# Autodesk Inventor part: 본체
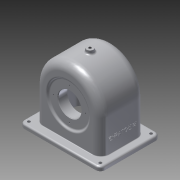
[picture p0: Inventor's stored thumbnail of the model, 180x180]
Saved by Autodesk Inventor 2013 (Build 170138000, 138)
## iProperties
Created: 2016-01
Part Number: 본체
Material: 알루미늄 6061
Document SubType Name: Modeling
Designer: cad10
Density: 2.40731 g/cm^3
Mass: 807.483 g
Surface Area: 1019.49 cm^2
Volume: 335.429 cm^3
Author: cad10
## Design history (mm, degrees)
sketch "스케치1"
  geometry: L1 (57, 0)-(57, -64); L2 (57, -64)-(-57, -64); L3 (-57, -64)-(-57, 0); L4 (0, 12.214)-(0, 34.551); A1 r 57 centre (0, 0) between (57, 0) and (-57, 0); 1 further point
  constraints: 8 end point, 2 parallel, 2 point on circle, 1 centre point, 1 coincident, 1 other
  dimensions: "d1" = 57 radius of A1; "d3" = 114 distance of L3.end L1.start; "d4" = 64 distance of L1.start L1.end
extrude "돌출1" new body sketch "스케치1" distance "d5" = 77; taper "d6" = 0 deg
node "작업 평면1"
sketch "스케치2"
  geometry: L1 (57, 0)-(-57, 0) reference; L2 (-57, 0)-(-57, 77) reference; L3 (57, 0)-(57, 77) reference; L4 (57, 77)-(-57, 77) reference; L5 (0, 0)-(0, 77); L6 (-57, 38.5)-(57, 38.5); L7 (-62, 90.5)-(62, 90.5); L8 (70, 82.5)-(70, -5.5); L9 (62, -13.5)-(-62, -13.5); L10 (-70, -5.5)-(-70, 82.5); A1 r 8 centre (-62, 82.5) between (-62, 90.5) and (-70, 82.5); A2 r 8 centre (62, 82.5) between (70, 82.5) and (62, 90.5); A3 r 8 centre (62, -5.5) between (62, -13.5) and (70, -5.5); A4 r 8 centre (-62, -5.5) between (-70, -5.5) and (-62, -13.5); 3 further points
  constraints: 12 end point, 8 point on circle, 8 tangent, 6 point on line, 4 centre point, 3 equal radius, 3 midpoint, 2 parallel, 1 horizontal, 1 perpendicular, 2 other
  dimensions: "d10" = 104 distance of point (70, 90.5) point (70, -13.5); "d11" = 140 distance of point (70, -13.5) point (-70, -13.5); "d13" = 8 radius of A1
extrude "돌출2" join sketch "스케치2" distance "d14" = 7; taper "d15" = 0 deg
sketch "스케치3"
  geometry: C1 r 2.5 at (-62, -5.5); C2 r 2.5 at (-62, 82.5); C3 r 2.5 at (62, 82.5); C4 r 2.5 at (62, -5.5); A1 r 8 centre (-62, 82.5) between (-62, 90.5) and (-70, 82.5) reference; A2 r 8 centre (-62, -5.5) between (-70, -5.5) and (-62, -13.5) reference; A3 r 8 centre (62, -5.5) between (62, -13.5) and (70, -5.5) reference; A4 r 8 centre (62, 82.5) between (70, 82.5) and (62, 90.5) reference; 1 further point
  constraints: 4 centre point, 4 coincident
  dimensions: "d16" = 5 diameter of C1; "d18" = 5 diameter of C2; "d19" = 5 diameter of C3; "d20" = 5 diameter of C4
extrude "돌출3" cut sketch "스케치3" distance "d21" = 7; taper "d22" = 0 deg
node "작업축1"
node "작업 평면2"
sketch "스케치5"
  geometry: L1 (-51, 0)-(-51, -76.657); L2 (51, 0)-(49.387, -76.657); L3 (49.387, -76.657)-(-51, -76.657); A1 r 51 centre (0, 0) between (50.955, -2.145) and (-51, 0); 1 further point
  constraints: 6 end point, 3 point on circle, 1 centre point, 1 coincident, 1 perpendicular, 1 point on line, 1 tangent, 1 vertical
  dimensions: "d33" = 102 diameter of A1
extrude "돌출4" cut sketch "스케치5" distance "d35" = 67; taper "d36" = 0 deg
sketch "스케치6"
  geometry: L1 (-16.832, -4)-(105.044, -4); L2 (72, -64)-(5, -64) reference; L3 (19, -4)-(19, 24); L4 (19, 24)-(2.235, 38.067); L5 (2.235, 38.067)-(2.235, -4); L6 (19, -4)-(2.235, -4); L7 (0, 0)-(0, 57) reference; 1 further point
  constraints: 10 end point, 2 perpendicular, 2 point on line, 1 coincident, 1 collinear, 1 horizontal
  dimensions: "d37" = 60 distance between parallel lines of L1 L2; "d39" = 50 deg angle of L4 L3; "d40" = 56 diameter of point (19, 24) L1; "d109" = 19 distance between parallel lines of L3 L7
revolve "회전1" sketch "스케치6" stored, may be unused: angle "d41" = 90 deg
node "작업 평면3"
sketch "스케치7"
  geometry: L1 (-57, 0)-(-57, 77) reference; L2 (57, 0)-(57, 77) reference; L3 (-57, 38.5)-(57, 38.5); C1 r 6 at (0, 38.5); 1 further point
  constraints: 2 end point, 2 midpoint, 1 centre point, 1 vertical alignment
  dimensions: "d43" = 12 diameter of C1; "d45" = 38.5 distance of C1.centre point (0, 0)
extrude "돌출5" join sketch "스케치7" stored distance "d46" = 67; taper "d47" = 0 deg
sketch "스케치8"
  geometry: L1 (-62, 64)-(62, 64) reference; C1 r 31 at (0, 4); A1 r 57 centre (0, 0) between (-57, 0) and (57, 0) reference
  constraints: 1 centre point, 1 vertical alignment
  dimensions: "d48" = 62 diameter of C1; "d50" = 60 distance from line of C1.centre L1
extrude "돌출6" join sketch "스케치8" distance "d51" = 10; taper "d52" = 0 deg
node "작업축2"
sketch "스케치9"
  geometry: L1 (0, 33.416)-(3, 30.899); L2 (3, 30.899)-(3, -20.71); L3 (0, 0)-(0, 57) reference; L4 (5, 35.747)-(19, 24) reference; L5 (-34.3, -4)-(111.3, -4) reference; L6 (3, -4)-(0, -4); L7 (0, -4)-(0, 33.416); L8 (0, 57)-(0, 43)
  constraints: 10 end point, 5 point on line, 1 vertical
  dimensions: "d53" = 3 distance between parallel lines of L3 L2; "d54" = 50 deg angle of L1 L2; "d55" = 5 distance from line of L1 L4.start; "d107" = 14 distance of L3.end L8.end
revolve "회전2" sketch "스케치9" stored, may be unused: angle "d56" = 90 deg
sketch "스케치10"
  geometry: L1 (-34.32, -4)-(111.418, -4) reference; L2 (-6.987, 16)-(90.598, 16); L3 (-6.987, 16)-(-6.987, -4); L4 (90.598, 16)-(90.598, -4); L5 (90.598, -4)-(-6.987, -4); 1 further point
  constraints: 8 end point, 3 perpendicular, 2 point on line, 1 parallel
  dimensions: "d57" = 40 diameter of L2 L1
revolve "회전3" sketch "스케치10" stored, may be unused: angle "d58" = 90 deg
sketch "스케치11" dims "d59" = 56
  geometry: C1 r 34.899 at (0, 0) reference; 3 further points
  constraints: 1 coincident, 3 other
hole "구멍1" sketch "스케치11" at (28, 0) diameter "d61" = 2.459; stored, may be unused: countersink angle "d65" = 90 deg, drill point angle "d67" = 118 deg; dims "d62" = 7, "d63" = 4, "d64" = 2, "d66" = 9
sketch "스케치12" dims "d71" = 48
  geometry: C1 r 31 at (0, 0) reference; 3 further points
  constraints: 1 coincident, 1 vertical alignment, 2 other
hole "구멍2" sketch "스케치12" at (0, -24) diameter "d73" = 2.459; stored, may be unused: countersink angle "d77" = 90 deg, drill point angle "d79" = 118 deg; dims "d74" = 6, "d75" = 4, "d76" = 2, "d78" = 8
sketch "스케치13"
  geometry: C1 r 6 at (0, 0) reference; 2 further points
  constraints: 1 coincident
hole "구멍3" sketch "스케치13" at (0, 0) diameter "d83" = 4.459; stored, may be unused: countersink angle "d87" = 90 deg, drill point angle "d89" = 118 deg; dims "d84" = 25, "d85" = 4, "d86" = 2, "d88" = 26
fillet "모깎기1" dims "d90" = 9
fillet "모깎기2" dims "d91" = 9
fillet "모깎기3" dims "d92" = 14
fillet "모깎기4" dims "d93" = 1
fillet "모깎기5" dims "d94" = 3
chamfer "모따기1" distance "d95" = 1; stored, may be unused: second distance "d96" = 2, angle "d97" = 45 deg
chamfer "모따기2" distance "d98" = 1; stored, may be unused: second distance "d99" = 2, angle "d100" = 45 deg
node "작업 평면4"
sketch "스케치14"
  geometry: L1 (0, -14)-(56, -14) reference; L2 (64, 68.5)-(64, -19.5) reference; 2 further points
  constraints: 1 other
  dimensions: "d102" = 38 distance from line of L1 point (34, 24); "d103" = 30 distance from line of point (34, 24) L2
feature "엠보싱1" sketch "스케치14" dims "d10" = 104, "d11" = 140, "d13" = 8, "d104" = 0.5, "d105" = 0
fillet "모깎기6" dims "d106" = 3
node "솔리드1"
pattern_circular "원형 패턴1" dims angle "d69" = 360 deg
pattern_circular "원형 패턴2" dims angle "d81" = 360 deg
other parameters: "d7" = -64, "d32" = -5, "d42" = 63, "d101" = 22.25
